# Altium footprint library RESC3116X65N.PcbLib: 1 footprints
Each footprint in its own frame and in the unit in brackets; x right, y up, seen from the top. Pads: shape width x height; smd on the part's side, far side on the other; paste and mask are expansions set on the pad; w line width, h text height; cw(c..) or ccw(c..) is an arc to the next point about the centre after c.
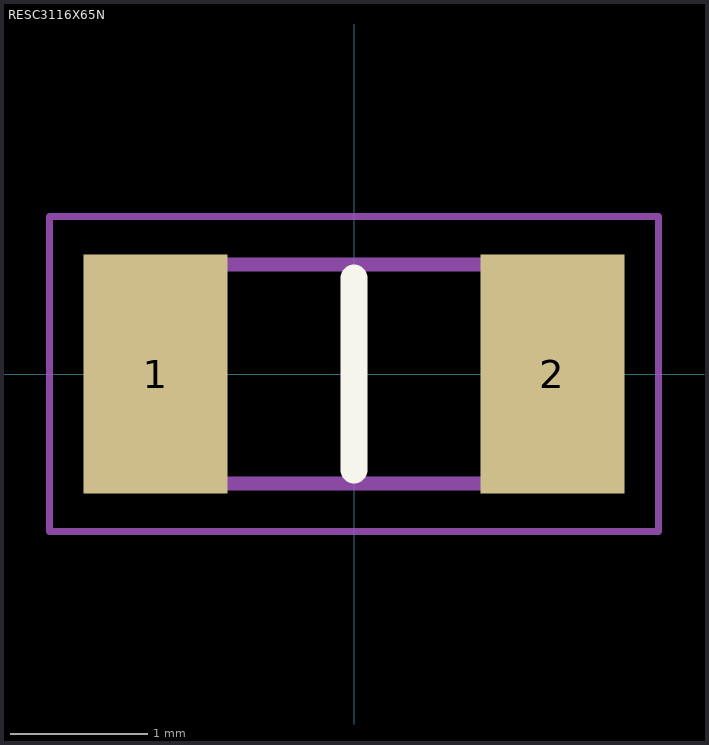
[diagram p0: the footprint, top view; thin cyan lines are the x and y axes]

## RESC3116X65N [mm]
pads (2):
  rect 1.05x1.75 smd: 1(-1.45,0) 2(1.45,0)
Top Overlay:
  lines w0.2: 0,-0.7 0,0.7
Mechanical 15:
  lines w0.1: -1.55,-0.8 1.55,-0.8 1.55,0.8 -1.55,0.8 -1.55,-0.8
Mechanical 20:
  lines w0.05: -2.225,-1.15 2.225,-1.15 2.225,1.15 -2.225,1.15 -2.225,-1.15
